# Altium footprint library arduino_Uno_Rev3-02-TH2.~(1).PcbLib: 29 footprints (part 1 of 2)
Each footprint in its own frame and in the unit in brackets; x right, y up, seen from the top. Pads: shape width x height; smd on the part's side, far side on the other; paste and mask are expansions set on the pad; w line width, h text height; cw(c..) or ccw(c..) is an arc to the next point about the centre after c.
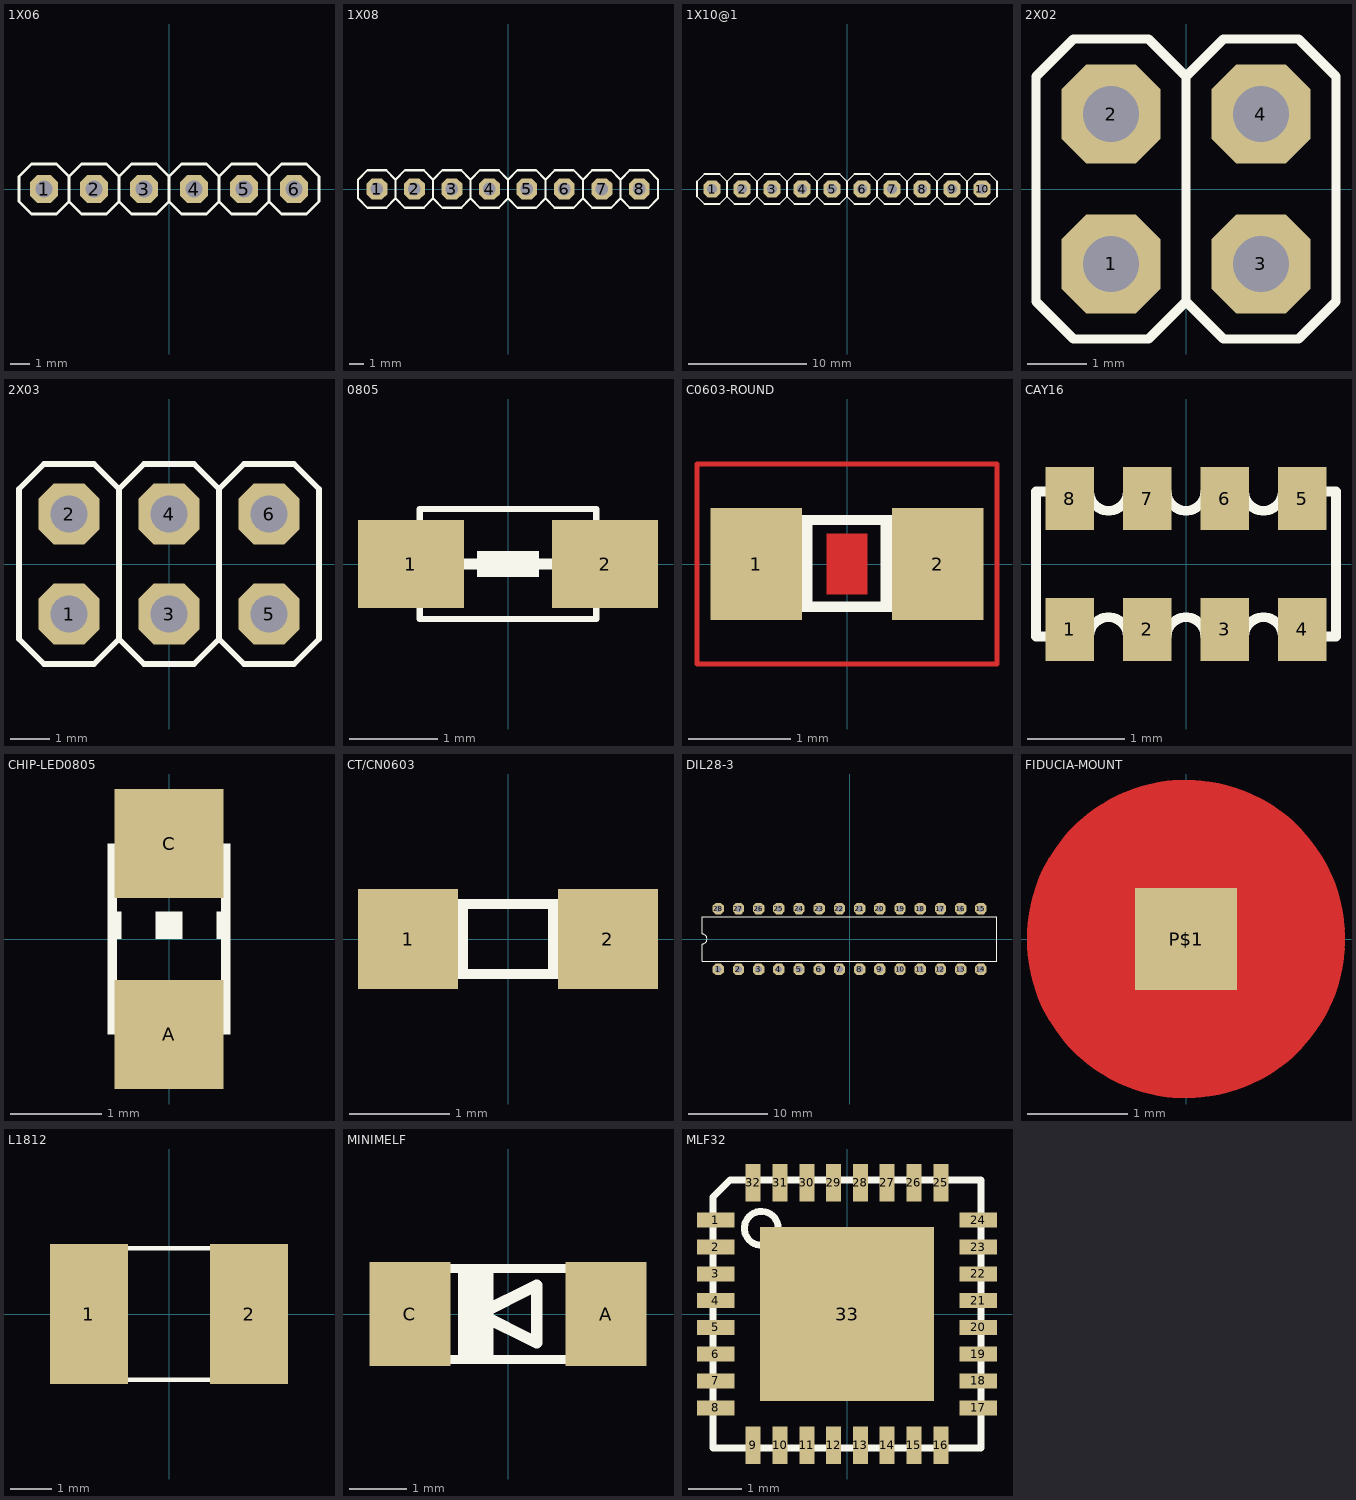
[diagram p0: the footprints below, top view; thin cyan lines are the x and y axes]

## 1X06 [mil]
pads (6):
  oct 56x56 hole 33.46: 1(-250,0) 2(-150,0) 3(-50,0) 4(50,0) 5(150,0) 6(250,0)
Top Overlay:
  rectangle: 240,-10 260,10
  rectangle: -260,-10 -240,10
  rectangle: -160,-10 -140,10
  rectangle: -60,-10 -40,10
  rectangle: 40,-10 60,10
  rectangle: 140,-10 160,10
  lines w6: -200,-25 -175,-50 -125,-50 -100,-25 ; -200,-25 -225,-50 -275,-50 -300,-25 -300,25 -275,50 -225,50 -200,25 ; -200,-25 -200,25 ; -200,25 -175,50 -125,50 -100,25 ; -100,-25 -100,25 ; -100,-25 -75,-50 -25,-50 0,-25 ; -100,25 -75,50 -25,50 0,25 ; 0,-25 25,-50 75,-50 100,-25 ; 0,-25 0,25 ; 0,25 25,50 75,50 100,25 ; 100,-25 125,-50 175,-50 200,-25 ; 100,-25 100,25 ; 100,25 125,50 175,50 200,25 ; 200,-25 225,-50 275,-50 300,-25 300,25 275,50 225,50 200,25 ; 200,-25 200,25

## 1X08 [mil]
pads (8):
  oct 56x56 hole 33.46: 1(-350,0) 2(-250,0) 3(-150,0) 4(-50,0) 5(50,0) 6(150,0) 7(250,0) 8(350,0)
Top Overlay:
  rectangle: 240,-10 260,10
  rectangle: 140,-10 160,10
  rectangle: 40,-10 60,10
  rectangle: -60,-10 -40,10
  rectangle: -160,-10 -140,10
  rectangle: -260,-10 -240,10
  rectangle: -360,-10 -340,10
  rectangle: 340,-10 360,10
  lines w6: -300,-25 -300,25 ; -300,-25 -325,-50 -375,-50 -400,-25 -400,25 -375,50 -325,50 -300,25 ; -300,-25 -275,-50 -225,-50 -200,-25 ; -300,25 -275,50 -225,50 -200,25 ; -200,-25 -175,-50 -125,-50 -100,-25 ; -200,-25 -200,25 ; -200,25 -175,50 -125,50 -100,25 ; -100,-25 -100,25 ; -100,-25 -75,-50 -25,-50 0,-25 ; -100,25 -75,50 -25,50 0,25 ; 0,-25 0,25 ; 0,-25 25,-50 75,-50 100,-25 ; 0,25 25,50 75,50 100,25 ; 100,-25 125,-50 175,-50 200,-25 ; 100,-25 100,25 ; 100,25 125,50 175,50 200,25 ; 200,-25 200,25 ; 200,-25 225,-50 275,-50 300,-25 ; 200,25 225,50 275,50 300,25 ; 300,-25 300,25 ; 300,-25 325,-50 375,-50 400,-25 400,25 375,50 325,50 300,25

## 1X10@1 [mil]
pads (10):
  oct 56x56 hole 33.46: 1(-450,0) 2(-350,0) 3(-250,0) 4(-150,0) 5(-50,0) 6(50,0) 7(150,0) 8(250,0) 9(350,0) 10(450,0)
Top Overlay:
  rectangle: 340,-10 360,10
  rectangle: 240,-10 260,10
  rectangle: 140,-10 160,10
  rectangle: 40,-10 60,10
  rectangle: -60,-10 -40,10
  rectangle: -160,-10 -140,10
  rectangle: -260,-10 -240,10
  rectangle: -360,-10 -340,10
  rectangle: -460,-10 -440,10
  rectangle: 440,-10 460,10
  lines w6: -400,-25 -400,25 ; -400,-25 -425,-50 -475,-50 -500,-25 -500,25 -475,50 -425,50 -400,25 ; -400,-25 -375,-50 -325,-50 -300,-25 ; -400,25 -375,50 -325,50 -300,25 ; -300,-25 -275,-50 -225,-50 -200,-25 ; -300,-25 -300,25 ; -300,25 -275,50 -225,50 -200,25 ; -200,-25 -200,25 ; -200,-25 -175,-50 -125,-50 -100,-25 ; -200,25 -175,50 -125,50 -100,25 ; -100,-25 -100,25 ; -100,-25 -75,-50 -25,-50 0,-25 ; -100,25 -75,50 -25,50 0,25 ; 0,-25 25,-50 75,-50 100,-25 ; 0,-25 0,25 ; 0,25 25,50 75,50 100,25 ; 100,-25 100,25 ; 100,-25 125,-50 175,-50 200,-25 ; 100,25 125,50 175,50 200,25 ; 200,-25 200,25 ; 200,-25 225,-50 275,-50 300,-25 ; 200,25 225,50 275,50 300,25 ; 300,-25 325,-50 375,-50 400,-25 ; 300,-25 300,25 ; 300,25 325,50 375,50 400,25 ; 400,-25 400,25 ; 400,-25 425,-50 475,-50 500,-25 500,25 475,50 425,50 400,25

## 2X02 [mil]
pads (4):
  oct 66x66 hole 37.4: 1(-50,-50) 2(-50,50) 3(50,-50) 4(50,50)
Top Overlay:
  rectangle: -60,-60 -40,-40
  rectangle: -60,40 -40,60
  rectangle: 40,40 60,60
  rectangle: 40,-60 60,-40
  lines w6: 0,-75 -25,-100 -75,-100 -100,-75 -100,75 -75,100 -25,100 0,75 ; 0,-75 25,-100 75,-100 100,-75 100,75 75,100 25,100 0,75 ; 0,-75 0,75

## 2X03 [mm]
pads (6):
  oct 1.55x1.55 hole 0.95: 1(-2.54,-1.27) 2(-2.54,1.27) 3(0,-1.27) 4(0,1.27) 5(2.54,-1.27) 6(2.54,1.27)
Top Overlay:
  rectangle: -2.794,-1.524 -2.286,-1.016
  rectangle: -2.794,1.016 -2.286,1.524
  rectangle: -0.254,1.016 0.254,1.524
  rectangle: -0.254,-1.524 0.254,-1.016
  rectangle: 2.286,1.016 2.794,1.524
  rectangle: 2.286,-1.524 2.794,-1.016
  lines w0.152: -1.27,-1.905 -1.905,-2.54 -3.175,-2.54 -3.81,-1.905 -3.81,1.905 -3.175,2.54 -1.905,2.54 -1.27,1.905 ; -1.27,-1.905 -0.635,-2.54 0.635,-2.54 1.27,-1.905 ; -1.27,-1.905 -1.27,1.905 ; -1.27,1.905 -0.635,2.54 0.635,2.54 1.27,1.905 ; 1.27,-1.905 1.27,1.905 ; 1.27,-1.905 1.905,-2.54 3.175,-2.54 3.81,-1.905 3.81,1.905 3.175,2.54 1.905,2.54 1.27,1.905

## 0805 [mm]
pads (2):
  rect 1.2x1 smd: 1(-1.1,0) 2(1.1,0)
Top Overlay:
  rectangle: -0.35,-0.15 0.35,0.15
  lines w0.07: -1,-0.625 1,-0.625 1,0.625 -1,0.625 -1,-0.625
  lines w0.127: -1.3,0 1.2,0 ; -1.1,0 1.1,0

## C0603-ROUND [mil]
pads (2):
  rect 35.37x43.31 smd: 1(-35,0) 2(35,0)
Top Layer:
  rectangle: -7.87,-11.81 7.87,11.81
  lines w2: -57.99,-38.7 57.99,-38.7 57.99,38.7 -57.99,38.7 -57.99,-38.7
Top Overlay:
  rectangle: -33,-18.5 -13.31,18.91
  rectangle: 13,-18.5 32.69,18.91
  lines w4: -14.02,-16.5 14.02,-16.5 ; -14.02,17.01 14.02,17.01

## CAY16 [mm]
pads (8):
  rect 0.5x0.65 smd: 1(-1.2,-0.675) 2(-0.4,-0.675) 3(0.4,-0.675) 4(1.2,-0.675) 5(1.2,0.675) 6(0.4,0.675) 7(-0.4,0.675) 8(-1.2,0.675)
Top Overlay:
  lines w0.102: -0.6,-0.75 ccw(c-0.8,-0.75) -1,-0.75 -1.55,-0.75 -1.55,0.75 -1,0.75 ccw(c-0.8,0.75) -0.6,0.75 ; -0.6,-0.75 -0.2,-0.75 cw(c0,-0.75) 0.2,-0.75 0.6,-0.75 ; -0.6,0.75 -0.2,0.75 ccw(c0,0.75) 0.2,0.75 0.6,0.75 ; 0.6,-0.75 cw(c0.8,-0.75) 1,-0.75 1.55,-0.75 1.55,0.75 1,0.75 cw(c0.8,0.75) 0.6,0.75

## CHIP-LED0805 [mm]
pads (2):
  rect 1.2x1.2 smd: A(0,-1.05) C(0,1.05)
Top Overlay:
  rectangle: -0.675,0 -0.525,0.3
  rectangle: 0.525,0 0.675,0.3
  rectangle: -0.15,0 0.15,0.3
  rectangle: -0.675,0.45 0.675,1.05
  rectangle: -0.675,-1.05 0.675,-0.45
  lines w0.102: -0.625,-0.45 -0.625,0.45 ; 0.625,-0.475 0.625,0.45

## CT/CN0603 [mm]
pads (2):
  rect 1x1 smd: 1(-1,0) 2(1,0)
Top Overlay:
  rectangle: -0.75,-0.35 -0.4,0.35
  region: 0.75,0.35 0.4,0.35 0.4,-0.35 0.75,-0.35
  lines w0.102: -0.75,-0.35 0.75,-0.35 0.75,0.35 -0.75,0.35 -0.75,-0.35

## DIL28-3 [mil]
pads (28):
  oct 56x56 hole 33.46: 1(-650,-150) 2(-550,-150) 3(-450,-150) 4(-350,-150) 5(-250,-150) 6(-150,-150) 7(-50,-150) 8(50,-150) 9(150,-150) 10(250,-150) 11(350,-150) 12(450,-150) 13(550,-150) 14(650,-150) 15(650,150) 16(550,150) 17(450,150) 18(350,150) 19(250,150) 20(150,150) 21(50,150) 22(-50,150) 23(-150,150) 24(-250,150) 25(-350,150) 26(-450,150) 27(-550,150) 28(-650,150)
Top Overlay:
  lines w6: -730,-110 -730,-25 ccw(c-730,0) -730,25 -730,110 730,110 730,-110 -730,-110

## DISCLAIMER [mil]

## FIDUCIA-MOUNT [mil]
pads (1):
  rect 40x40 smd: P$1(0,0)
Top Layer:
  circle w5: c0,0 r59.06
  circle w86: c0,0 r19.68

## L1812 [mm]
pads (2):
  rect 1.9x3.4 smd: 1(-1.95,0) 2(1.95,0)
Top Overlay:
  rectangle: -2.388,-1.651 -1.438,1.649
  rectangle: 1.448,-1.651 2.398,1.649
  lines w0.102: -1.473,1.6 1.473,1.6 ; -1.448,-1.6 1.473,-1.6

## MINIMELF [mm]
pads (2):
  rect 1.4x1.8 smd: A(1.7,0) C(-1.7,0)
Top Overlay:
  rectangle: -1.854,-0.864 -1.295,0.864
  rectangle: 1.295,-0.864 1.854,0.864
  rectangle: -0.864,-0.787 -0.254,0.787
  lines w0.152: -1.321,-0.787 1.321,-0.787 ; -1.321,0.787 1.321,0.787
  lines w0.203: -0.5,0 0.5,0.5 0.5,-0.5 -0.5,0

## MLF32 [mm]
pads (33):
  rect 0.7x0.28 smd: 1(-2.45,1.75) 2(-2.45,1.25) 3(-2.45,0.75) 4(-2.45,0.25) 5(-2.45,-0.25) 6(-2.45,-0.75) 7(-2.45,-1.25) 8(-2.45,-1.75) 17(2.45,-1.75) 18(2.45,-1.25) 19(2.45,-0.75) 20(2.45,-0.25) 21(2.45,0.25) 22(2.45,0.75) 23(2.45,1.25) 24(2.45,1.75)
  rect 0.28x0.7 smd: 9(-1.75,-2.45) 10(-1.25,-2.45) 11(-0.75,-2.45) 12(-0.25,-2.45) 13(0.25,-2.45) 14(0.75,-2.45) 15(1.25,-2.45) 16(1.75,-2.45) 25(1.75,2.45) 26(1.25,2.45) 27(0.75,2.45) 28(0.25,2.45) 29(-0.25,2.45) 30(-0.75,2.45) 31(-1.25,2.45) 32(-1.75,2.45)
  rect 3.254x3.254 smd: 33(0,0)
Top Layer:
  rectangle: -0.635,-0.635 0.635,0.635
Top Overlay:
  circle w0.127: c-1.6,1.6 r0.316
  lines w0.127: -2.5,-2.5 2.5,-2.5 2.5,2.5 -2.183,2.5 -2.5,2.183 -2.5,-2.5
